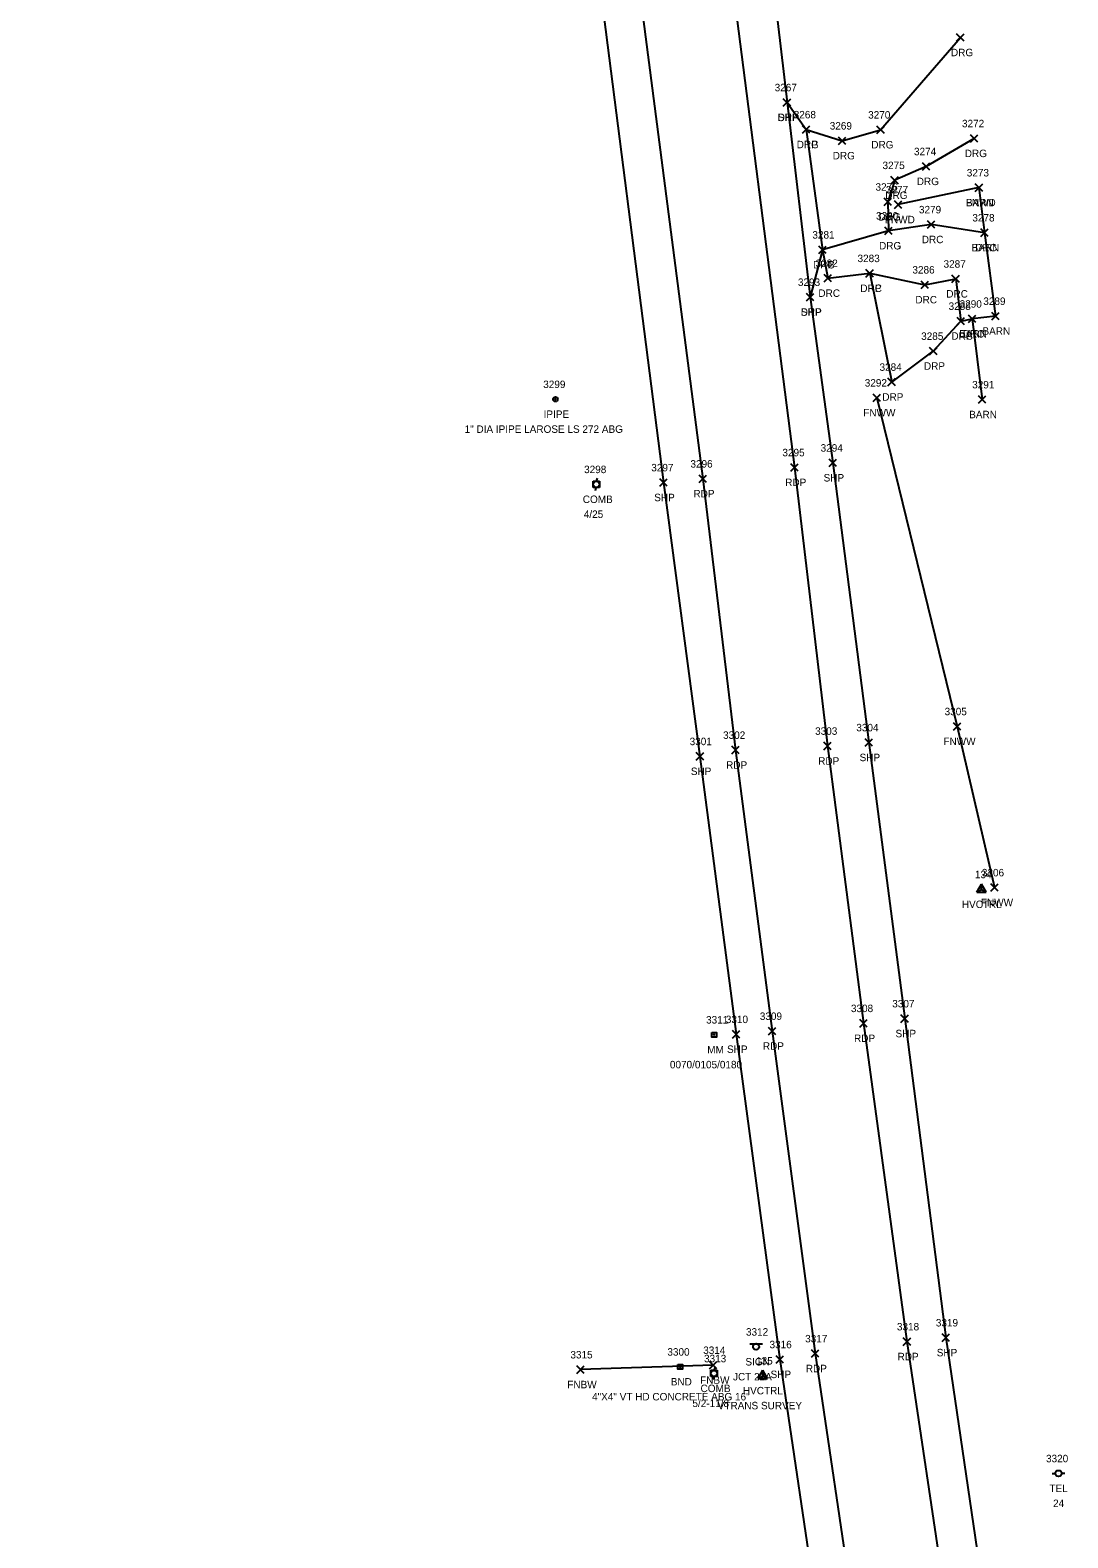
# Model space of a CAD drawing. Extents: x 1443071 to 1445292, y 614024 to 622563.
# Drawn here: x 1444280.5 to 1444558.5, y 615614.1 to 616018.1 of the extents above; entities that cross this region are included whole.
import ezdxf

# ---------------------------------------------------------------- set-up
doc = ezdxf.new("R2010")
doc.units = 0
for name, color, linetype in [('C_A', 7, 'Continuous'), ('C_C', 7, 'Continuous'), ('C_I', 7, 'Continuous'), ('CPSM', 7, 'Continuous'), ('L_A', 7, 'Continuous'), ('L_I', 7, 'Continuous'), ('L_TIC', 7, 'Continuous'), ('LBC', 7, 'Continuous'), ('LFNC', 7, 'Continuous'), ('M_A', 7, 'Continuous'), ('M_C', 7, 'Continuous'), ('M_I', 7, 'Continuous'), ('MHBP', 7, 'Continuous'), ('MPIP', 7, 'Continuous'), ('P_A', 7, 'Continuous'), ('P_I', 7, 'Continuous'), ('P_TIC', 7, 'Continuous'), ('PET', 7, 'Continuous'), ('PSP', 7, 'Continuous'), ('R_A', 7, 'Continuous'), ('R_I', 7, 'Continuous'), ('R_TIC', 7, 'Continuous'), ('RDG', 7, 'Continuous'), ('RDP', 7, 'Continuous'), ('S_A', 7, 'Continuous'), ('S_C', 7, 'Continuous'), ('S_I', 7, 'Continuous'), ('SRM', 7, 'Continuous'), ('SSGN', 7, 'Continuous'), ('U_A', 7, 'Continuous'), ('U_C', 7, 'Continuous'), ('U_I', 7, 'Continuous'), ('UP', 7, 'Continuous')]:
    doc.layers.add(name, color=color, linetype=linetype)

msp = doc.modelspace()

# ---------------------------------------------------------------- linework, layer by layer
at = {"layer": 'CPSM'}
for p, q in [((1444534.17, 615787.11), (1444535.42, 615789.27)), ((1444534.17, 615787.11), (1444535.42, 615787.83)), ((1444536.67, 615787.11), (1444535.42, 615789.27)), ((1444535.42, 615787.83), (1444535.42, 615789.27)), ((1444535.42, 615787.83), (1444535.42, 615787.83)), ((1444535.42, 615787.83), (1444536.67, 615787.11)), ((1444534.17, 615787.11), (1444536.67, 615787.11)), ((1444475.52, 615656.78), (1444476.77, 615658.95)), ((1444478.02, 615656.78), (1444476.77, 615658.95)), ((1444476.77, 615657.5), (1444476.77, 615658.95)), ((1444475.52, 615656.78), (1444476.77, 615657.5)), ((1444475.52, 615656.78), (1444478.02, 615656.78)), ((1444476.77, 615657.5), (1444476.77, 615657.5)), ((1444476.77, 615657.5), (1444478.02, 615656.78))]:
    msp.add_line(p, q, dxfattribs=at)
at = {"layer": 'L_TIC'}
for points in [[(1444533.7, 615974.89), (1444535.7, 615976.89)], [(1444535.7, 615974.89), (1444533.7, 615976.89)], [(1444533.7, 615974.89), (1444535.7, 615976.89)], [(1444535.7, 615974.89), (1444533.7, 615976.89)], [(1444512.03, 615970.34), (1444514.03, 615972.34)], [(1444514.03, 615970.34), (1444512.03, 615972.34)], [(1444535.19, 615962.82), (1444537.19, 615964.82)], [(1444537.19, 615962.82), (1444535.19, 615964.82)], [(1444531.86, 615939.72), (1444533.86, 615941.72)], [(1444533.86, 615939.72), (1444531.86, 615941.72)], [(1444538.13, 615940.46), (1444540.13, 615942.46)], [(1444540.13, 615940.46), (1444538.13, 615942.46)], [(1444506.36, 615918.58), (1444508.36, 615920.58)], [(1444508.36, 615918.58), (1444506.36, 615920.58)], [(1444534.57, 615918.09), (1444536.57, 615920.09)], [(1444536.57, 615918.09), (1444534.57, 615920.09)], [(1444527.84, 615830.5), (1444529.84, 615832.5)], [(1444529.84, 615830.5), (1444527.84, 615832.5)], [(1444537.88, 615787.32), (1444539.88, 615789.32)], [(1444539.88, 615787.32), (1444537.88, 615789.32)], [(1444426.94, 615658.13), (1444428.94, 615660.13)], [(1444428.94, 615658.13), (1444426.94, 615660.13)], [(1444462.51, 615659.33), (1444464.51, 615661.33)], [(1444464.51, 615659.33), (1444462.51, 615661.33)]]:
    msp.add_lwpolyline(points, dxfattribs=at)
at = {"layer": 'LBC'}
msp.add_lwpolyline([(1444534.7, 615975.89), (1444536.19, 615963.82), (1444539.13, 615941.46), (1444532.86, 615940.72), (1444535.57, 615919.09)], dxfattribs=at)
at = {"layer": 'LFNC'}
for points in [[(1444534.7, 615975.89), (1444513.03, 615971.34)], [(1444507.36, 615919.58), (1444528.84, 615831.5), (1444538.88, 615788.32)], [(1444463.51, 615660.33), (1444427.94, 615659.13)]]:
    msp.add_lwpolyline(points, dxfattribs=at)
at = {"layer": 'MHBP'}
msp.add_lwpolyline([(1444454.02, 615660.5), (1444455.27, 615660.5), (1444455.27, 615659.25), (1444454.02, 615659.25)], close=True, dxfattribs=at)
msp.add_circle((1444454.64, 615659.88), 0.0833, dxfattribs=at)
at = {"layer": 'MPIP'}
for radius in [0.625, 0.0833]:
    msp.add_circle((1444421.23, 615919.18), radius, dxfattribs=at)
at = {"layer": 'P_TIC'}
for points in [[(1444482.28, 615997.72), (1444484.28, 615999.72)], [(1444484.28, 615997.72), (1444482.28, 615999.72)], [(1444488.46, 615945.55), (1444490.46, 615947.55)], [(1444490.46, 615945.55), (1444488.46, 615947.55)], [(1444484.3, 615899.9), (1444486.3, 615901.9)], [(1444486.3, 615899.9), (1444484.3, 615901.9)], [(1444494.54, 615901.14), (1444496.54, 615903.14)], [(1444496.54, 615901.14), (1444494.54, 615903.14)], [(1444449.17, 615895.86), (1444451.17, 615897.86)], [(1444451.17, 615895.86), (1444449.17, 615897.86)], [(1444459.71, 615896.87), (1444461.71, 615898.87)], [(1444461.71, 615896.87), (1444459.71, 615898.87)], [(1444504.18, 615826.19), (1444506.18, 615828.19)], [(1444506.18, 615826.19), (1444504.18, 615828.19)], [(1444458.96, 615822.48), (1444460.96, 615824.48)], [(1444460.96, 615822.48), (1444458.96, 615824.48)], [(1444468.48, 615824.17), (1444470.48, 615826.17)], [(1444470.48, 615824.17), (1444468.48, 615826.17)], [(1444493.14, 615825.26), (1444495.14, 615827.26)], [(1444495.14, 615825.26), (1444493.14, 615827.26)], [(1444502.74, 615750.94), (1444504.74, 615752.94)], [(1444504.74, 615750.94), (1444502.74, 615752.94)], [(1444513.81, 615752.2), (1444515.81, 615754.2)], [(1444515.81, 615752.2), (1444513.81, 615754.2)], [(1444468.66, 615748), (1444470.66, 615750)], [(1444470.66, 615748), (1444468.66, 615750)], [(1444478.32, 615748.85), (1444480.32, 615750.85)], [(1444480.32, 615748.85), (1444478.32, 615750.85)], [(1444514.41, 615665.64), (1444516.41, 615667.64)], [(1444516.41, 615665.64), (1444514.41, 615667.64)], [(1444524.85, 615666.7), (1444526.85, 615668.7)], [(1444526.85, 615666.7), (1444524.85, 615668.7)], [(1444480.34, 615660.86), (1444482.34, 615662.86)], [(1444482.34, 615660.86), (1444480.34, 615662.86)], [(1444489.82, 615662.43), (1444491.82, 615664.43)], [(1444491.82, 615662.43), (1444489.82, 615664.43)]]:
    msp.add_lwpolyline(points, dxfattribs=at)
at = {"layer": 'PET'}
for points in [[(1444290.04, 617226.49), (1444293.29, 617200.68), (1444305.86, 617102.26), (1444318.1, 617012.36), (1444328.61, 616929.53), (1444340.48, 616832.7), (1444349.36, 616766.46), (1444359.48, 616687.73), (1444375.76, 616559.26), (1444386.72, 616474.82), (1444392.98, 616424.11), (1444399.64, 616374.74), (1444405.35, 616331.68), (1444416.25, 616246.74), (1444430.45, 616134.64), (1444440.68, 616052.2), (1444460.71, 615897.87), (1444469.48, 615825.17), (1444479.32, 615749.85), (1444490.82, 615663.43), (1444501.1, 615593.99)], [(1444314.9, 617227.6), (1444331.28, 617099.37), (1444342.74, 617014.98), (1444353.45, 616933.43), (1444365.99, 616834.42), (1444373.87, 616769.68), (1444384.25, 616690.54), (1444399.86, 616561.36), (1444411.32, 616477.78), (1444418.43, 616426.72), (1444433.04, 616320.39), (1444440.5, 616248.61), (1444455.15, 616137.88), (1444465.57, 616054.84), (1444485.3, 615900.9), (1444494.14, 615826.26), (1444503.74, 615751.94), (1444515.41, 615666.64), (1444525.64, 615597.72)]]:
    msp.add_lwpolyline(points, dxfattribs=at)
at = {"layer": 'PSP'}
for points in [[(1444280.5, 617226.12), (1444283.66, 617200.61), (1444293.17, 617127.11), (1444296.38, 617100.83), (1444308.28, 617010.91), (1444318.74, 616928.98), (1444325.56, 616872.02), (1444335.05, 616795.34), (1444338.72, 616765.27), (1444349.45, 616686.56), (1444353.22, 616653.3), (1444364.91, 616559.25), (1444375.85, 616473.62), (1444383.24, 616422.24), (1444388.01, 616382.64), (1444395.12, 616329.81), (1444406.01, 616244.88), (1444420.16, 616134.13), (1444430.49, 616051.12), (1444450.17, 615896.86), (1444459.96, 615823.48), (1444469.66, 615749), (1444481.34, 615661.86), (1444491.6, 615592.34)], [(1444325.72, 617229.34), (1444331.18, 617190.03), (1444341.63, 617111.11), (1444353.65, 617016.1), (1444364.55, 616934.22), (1444377.14, 616835.48), (1444385.64, 616770.75), (1444395.97, 616692.96), (1444412.43, 616562.03), (1444423.01, 616481.11), (1444430.88, 616420.51), (1444443.11, 616323.39), (1444448.99, 616268.44), (1444454, 616230.8), (1444465.61, 616141.36), (1444476.5, 616056.13), (1444483.28, 615998.72), (1444489.46, 615946.55), (1444495.54, 615902.14), (1444505.18, 615827.19), (1444514.81, 615753.2), (1444525.85, 615667.7), (1444535.69, 615600.77)]]:
    msp.add_lwpolyline(points, dxfattribs=at)
at = {"layer": 'R_TIC'}
for points in [[(1444528.71, 616015.11), (1444530.71, 616017.11)], [(1444530.71, 616015.11), (1444528.71, 616017.11)], [(1444482.28, 615997.72), (1444484.28, 615999.72)], [(1444484.28, 615997.72), (1444482.28, 615999.72)], [(1444487.38, 615990.45), (1444489.38, 615992.45)], [(1444489.38, 615990.45), (1444487.38, 615992.45)], [(1444487.38, 615990.45), (1444489.38, 615992.45)], [(1444489.38, 615990.45), (1444487.38, 615992.45)], [(1444497.03, 615987.46), (1444499.03, 615989.46)], [(1444499.03, 615987.46), (1444497.03, 615989.46)], [(1444507.36, 615990.4), (1444509.36, 615992.4)], [(1444509.36, 615990.4), (1444507.36, 615992.4)], [(1444532.41, 615988.07), (1444534.41, 615990.07)], [(1444534.41, 615988.07), (1444532.41, 615990.07)], [(1444519.55, 615980.57), (1444521.55, 615982.57)], [(1444521.55, 615980.57), (1444519.55, 615982.57)], [(1444511.12, 615976.86), (1444513.12, 615978.86)], [(1444513.12, 615976.86), (1444511.12, 615978.86)], [(1444509.29, 615971.07), (1444511.29, 615973.07)], [(1444511.29, 615971.07), (1444509.29, 615973.07)], [(1444509.45, 615963.33), (1444511.45, 615965.33)], [(1444511.45, 615963.33), (1444509.45, 615965.33)], [(1444509.45, 615963.33), (1444511.45, 615965.33)], [(1444511.45, 615963.33), (1444509.45, 615965.33)], [(1444520.89, 615965), (1444522.89, 615967)], [(1444522.89, 615965), (1444520.89, 615967)], [(1444535.19, 615962.82), (1444537.19, 615964.82)], [(1444537.19, 615962.82), (1444535.19, 615964.82)], [(1444491.76, 615958.24), (1444493.76, 615960.24)], [(1444493.76, 615958.24), (1444491.76, 615960.24)], [(1444491.76, 615958.24), (1444493.76, 615960.24)], [(1444493.76, 615958.24), (1444491.76, 615960.24)], [(1444504.43, 615951.93), (1444506.43, 615953.93)], [(1444506.43, 615951.93), (1444504.43, 615953.93)], [(1444504.43, 615951.93), (1444506.43, 615953.93)], [(1444506.43, 615951.93), (1444504.43, 615953.93)], [(1444493.19, 615950.62), (1444495.19, 615952.62)], [(1444495.19, 615950.62), (1444493.19, 615952.62)], [(1444519.19, 615948.87), (1444521.19, 615950.87)], [(1444521.19, 615948.87), (1444519.19, 615950.87)], [(1444527.47, 615950.43), (1444529.47, 615952.43)], [(1444529.47, 615950.43), (1444527.47, 615952.43)], [(1444488.46, 615945.55), (1444490.46, 615947.55)], [(1444490.46, 615945.55), (1444488.46, 615947.55)], [(1444528.83, 615939.13), (1444530.83, 615941.13)], [(1444530.83, 615939.13), (1444528.83, 615941.13)], [(1444528.83, 615939.13), (1444530.83, 615941.13)], [(1444530.83, 615939.13), (1444528.83, 615941.13)], [(1444531.86, 615939.72), (1444533.86, 615941.72)], [(1444533.86, 615939.72), (1444531.86, 615941.72)], [(1444521.47, 615931.09), (1444523.47, 615933.09)], [(1444523.47, 615931.09), (1444521.47, 615933.09)], [(1444510.32, 615922.8), (1444512.32, 615924.8)], [(1444512.32, 615922.8), (1444510.32, 615924.8)]]:
    msp.add_lwpolyline(points, dxfattribs=at)
at = {"layer": 'RDG'}
for points in [[(1444488.38, 615991.45), (1444498.03, 615988.46), (1444508.36, 615991.4), (1444529.71, 616016.11)], [(1444533.41, 615989.07), (1444520.55, 615981.57), (1444512.12, 615977.86), (1444510.29, 615972.07), (1444510.45, 615964.33)]]:
    msp.add_lwpolyline(points, dxfattribs=at)
at = {"layer": 'RDP'}
for points in [[(1444483.28, 615998.72), (1444488.38, 615991.45), (1444492.76, 615959.24), (1444489.46, 615946.55)], [(1444536.19, 615963.82), (1444521.89, 615966), (1444510.45, 615964.33), (1444492.76, 615959.24), (1444494.19, 615951.62), (1444505.43, 615952.93), (1444520.19, 615949.87), (1444528.47, 615951.43), (1444529.83, 615940.13), (1444532.86, 615940.72)], [(1444505.43, 615952.93), (1444511.32, 615923.8), (1444522.47, 615932.09), (1444529.83, 615940.13)]]:
    msp.add_lwpolyline(points, dxfattribs=at)
at = {"layer": 'SRM'}
msp.add_lwpolyline([(1444463.09, 615749.5), (1444464.34, 615749.5), (1444464.34, 615748.25), (1444463.09, 615748.25)], close=True, dxfattribs=at)
msp.add_circle((1444463.72, 615748.88), 0.0833, dxfattribs=at)
at = {"layer": 'SSGN'}
for p, q in [((1444473.35, 615666.09), (1444476.68, 615666.09)), ((1444475, 615665.26), (1444475, 615665.26))]:
    msp.add_line(p, q, dxfattribs=at)
msp.add_circle((1444475, 615665.26), 0.833, dxfattribs=at)
at = {"layer": 'UP'}
for p, q in [((1444431.34, 615895.55), (1444431.34, 615897.21)), ((1444431.34, 615897.21), (1444433, 615897.21)), ((1444432.42, 615898.05), (1444432.17, 615897.21)), ((1444432.17, 615896.38), (1444432.17, 615896.38)), ((1444433, 615897.21), (1444433, 615895.55)), ((1444433, 615895.55), (1444431.34, 615895.55)), ((1444431.92, 615894.71), (1444432.17, 615895.55)), ((1444462.9, 615657.28), (1444462.9, 615658.95)), ((1444462.9, 615658.95), (1444464.56, 615658.95)), ((1444463.98, 615659.78), (1444463.73, 615658.95)), ((1444463.73, 615658.11), (1444463.73, 615658.11)), ((1444464.56, 615658.95), (1444464.56, 615657.28)), ((1444464.56, 615657.28), (1444462.9, 615657.28)), ((1444463.48, 615656.45), (1444463.73, 615657.28)), ((1444554.35, 615631.3), (1444555.18, 615631.3)), ((1444556.01, 615631.31), (1444556.01, 615631.31)), ((1444557.68, 615631.31), (1444556.85, 615631.31)), ((1444556.85, 615631.31), (1444556.85, 615631.31)), ((1444557.68, 615631.31), (1444557.68, 615631.31))]:
    msp.add_line(p, q, dxfattribs=at)
for centre in [(1444432.17, 615896.38), (1444463.73, 615658.11), (1444556.01, 615631.31)]:
    msp.add_circle(centre, 0.833, dxfattribs=at)

# ---------------------------------------------------------------- texts
at = {"layer": 'C_A'}
for p in [(1444530.11, 615782.83), (1444471.46, 615652.5)]:
    msp.add_text('HVCTRL', height=2, dxfattribs=at).set_placement(p)
at = {"layer": 'C_C'}
msp.add_text('VTRANS SURVEY', height=2, dxfattribs=at).set_placement((1444464.71, 615648.5))
at = {"layer": 'C_I'}
for s, p in [('134', (1444533.62, 615790.83)), ('135', (1444474.98, 615660.5))]:
    msp.add_text(s, height=2, dxfattribs=at).set_placement(p)
at = {"layer": 'L_A'}
for s, p in [('FNWD', (1444531.16, 615970.89)), ('BARN', (1444531.21, 615970.89)), ('FNWD', (1444509.5, 615966.34)), ('BARN', (1444532.7, 615958.82)), ('BARN', (1444529.38, 615935.72)), ('BARN', (1444535.64, 615936.46)), ('FNWW', (1444503.71, 615914.58)), ('BARN', (1444532.08, 615914.09)), ('FNWW', (1444525.18, 615826.5)), ('FNWW', (1444535.22, 615783.32)), ('FNBW', (1444424.41, 615654.13)), ('FNBW', (1444459.99, 615655.33))]:
    msp.add_text(s, height=2, dxfattribs=at).set_placement(p)
at = {"layer": 'L_I'}
for s, p in [('3273', (1444531.44, 615978.89)), ('3273', (1444531.44, 615978.89)), ('3277', (1444509.77, 615974.34)), ('3278', (1444532.93, 615966.82)), ('3290', (1444529.52, 615943.72)), ('3289', (1444535.86, 615944.46)), ('3292', (1444504.1, 615922.58)), ('3291', (1444532.88, 615922.09)), ('3305', (1444525.5, 615834.5)), ('3306', (1444535.48, 615791.32)), ('3315', (1444425.24, 615662.13)), ('3314', (1444460.82, 615663.33))]:
    msp.add_text(s, height=2, dxfattribs=at).set_placement(p)
at = {"layer": 'M_A'}
for s, p in [('IPIPE', (1444418.06, 615914.18)), ('BND', (1444452.13, 615654.88))]:
    msp.add_text(s, height=2, dxfattribs=at).set_placement(p)
at = {"layer": 'M_C'}
for s, p in [('1" DIA IPIPE LAROSE LS 272 ABG', (1444396.89, 615910.18)), ('4"X4" VT HD CONCRETE ABG 16"', (1444431.04, 615650.88))]:
    msp.add_text(s, height=2, dxfattribs=at).set_placement(p)
at = {"layer": 'M_I'}
for s, p in [('3299', (1444417.96, 615922.18)), ('3300', (1444451.22, 615662.88))]:
    msp.add_text(s, height=2, dxfattribs=at).set_placement(p)
at = {"layer": 'P_A'}
for s, p in [('SHP', (1444480.82, 615993.72)), ('SHP', (1444487, 615941.55)), ('RDP', (1444482.79, 615895.9)), ('SHP', (1444493.08, 615897.14)), ('SHP', (1444447.7, 615891.86)), ('RDP', (1444458.2, 615892.87)), ('SHP', (1444502.72, 615822.19)), ('SHP', (1444457.5, 615818.48)), ('RDP', (1444466.96, 615820.17)), ('RDP', (1444491.63, 615821.26)), ('RDP', (1444476.81, 615744.85)), ('RDP', (1444501.23, 615746.94)), ('SHP', (1444512.35, 615748.2)), ('SHP', (1444467.2, 615744)), ('RDP', (1444512.9, 615661.64)), ('SHP', (1444523.39, 615662.7)), ('SHP', (1444478.87, 615656.86)), ('RDP', (1444488.31, 615658.43))]:
    msp.add_text(s, height=2, dxfattribs=at).set_placement(p)
at = {"layer": 'P_I'}
for s, p in [('3267', (1444479.97, 616001.72)), ('3293', (1444486.2, 615949.55)), ('3295', (1444482.04, 615903.9)), ('3294', (1444492.28, 615905.14)), ('3297', (1444446.91, 615899.86)), ('3296', (1444457.4, 615900.87)), ('3304', (1444501.84, 615830.19)), ('3301', (1444457.19, 615826.48)), ('3302', (1444466.14, 615828.17)), ('3303', (1444490.8, 615829.26)), ('3308', (1444500.4, 615754.94)), ('3307', (1444511.47, 615756.2)), ('3310', (1444466.88, 615752)), ('3309', (1444475.98, 615752.85)), ('3318', (1444512.72, 615669.64)), ('3319', (1444523.15, 615670.7)), ('3316', (1444478.59, 615664.86)), ('3317', (1444488.13, 615666.43))]:
    msp.add_text(s, height=2, dxfattribs=at).set_placement(p)
at = {"layer": 'R_A'}
for s, p in [('DRG', (1444527.2, 616011.11)), ('DRP', (1444480.77, 615993.72)), ('DRG', (1444485.87, 615986.45)), ('DRP', (1444485.87, 615986.45)), ('DRG', (1444495.52, 615983.46)), ('DRG', (1444505.85, 615986.4)), ('DRG', (1444530.9, 615984.07)), ('DRG', (1444518.04, 615976.57)), ('DRG', (1444509.61, 615972.86)), ('DRG', (1444507.78, 615967.07)), ('DRC', (1444507.94, 615959.33)), ('DRG', (1444507.94, 615959.33)), ('DRC', (1444519.38, 615961)), ('DRC', (1444533.68, 615958.82)), ('DRC', (1444490.25, 615954.24)), ('DRP', (1444490.25, 615954.24)), ('DRC', (1444502.92, 615947.93)), ('DRP', (1444502.92, 615947.93)), ('DRC', (1444491.68, 615946.62)), ('DRC', (1444517.67, 615944.87)), ('DRC', (1444525.95, 615946.43)), ('DRP', (1444486.95, 615941.55)), ('DRC', (1444527.32, 615935.13)), ('DRP', (1444527.32, 615935.13)), ('DRC', (1444530.35, 615935.72)), ('DRP', (1444519.96, 615927.09)), ('DRP', (1444508.81, 615918.8))]:
    msp.add_text(s, height=2, dxfattribs=at).set_placement(p)
at = {"layer": 'R_I'}
for s, p in [('3267', (1444479.97, 616001.72)), ('3268', (1444485.07, 615994.45)), ('3268', (1444485.07, 615994.45)), ('3269', (1444494.72, 615991.46)), ('3270', (1444505.01, 615994.4)), ('3272', (1444530.15, 615992.07)), ('3274', (1444517.29, 615984.57)), ('3275', (1444508.86, 615980.86)), ('3276', (1444506.98, 615975.07)), ('3280', (1444507.11, 615967.33)), ('3280', (1444507.11, 615967.33)), ('3279', (1444518.62, 615969)), ('3278', (1444532.93, 615966.82)), ('3281', (1444490.07, 615962.24)), ('3281', (1444490.07, 615962.24)), ('3283', (1444502.17, 615955.93)), ('3283', (1444502.17, 615955.93)), ('3282', (1444490.93, 615954.62)), ('3286', (1444516.87, 615952.87)), ('3287', (1444525.21, 615954.43)), ('3293', (1444486.2, 615949.55)), ('3288', (1444526.57, 615943.13)), ('3288', (1444526.57, 615943.13)), ('3290', (1444529.52, 615943.72)), ('3285', (1444519.21, 615935.09)), ('3284', (1444508.06, 615926.8))]:
    msp.add_text(s, height=2, dxfattribs=at).set_placement(p)
at = {"layer": 'S_A'}
for s, p in [('MM', (1444461.9, 615743.88)), ('SIGN', (1444472.13, 615660.24))]:
    msp.add_text(s, height=2, dxfattribs=at).set_placement(p)
at = {"layer": 'S_C'}
for s, p in [('0070/0105/0180', (1444451.9, 615739.88)), ('JCT 22A', (1444468.81, 615656.24))]:
    msp.add_text(s, height=2, dxfattribs=at).set_placement(p)
at = {"layer": 'S_I'}
for s, p in [('3311', (1444461.59, 615751.88)), ('3312', (1444472.28, 615668.24))]:
    msp.add_text(s, height=2, dxfattribs=at).set_placement(p)
at = {"layer": 'U_A'}
for s, p in [('COMB', (1444428.56, 615891.38)), ('COMB', (1444460.11, 615653.11)), ('TEL', (1444553.57, 615626.31))]:
    msp.add_text(s, height=2, dxfattribs=at).set_placement(p)
at = {"layer": 'U_C'}
for s, p in [('4/25', (1444428.83, 615887.38)), ('5/2-11/8', (1444457.93, 615649.11)), ('24', (1444554.55, 615622.31))]:
    msp.add_text(s, height=2, dxfattribs=at).set_placement(p)
at = {"layer": 'U_I'}
for s, p in [('3298', (1444428.91, 615899.38)), ('3313', (1444461.04, 615661.11)), ('3320', (1444552.67, 615634.31))]:
    msp.add_text(s, height=2, dxfattribs=at).set_placement(p)

doc.saveas('drawing.dxf')
